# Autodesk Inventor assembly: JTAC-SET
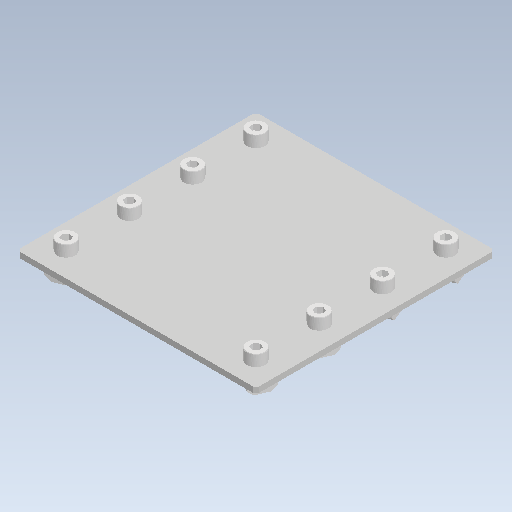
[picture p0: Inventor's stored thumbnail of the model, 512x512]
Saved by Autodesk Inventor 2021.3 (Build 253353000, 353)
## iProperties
Created: 2022-02
Part Number: JTAC-SET
Document SubType Name: Assembly
Designer: kengo
Author: kengo
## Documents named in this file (3)
- C:\Users\kengo\Documents\S2S_frame\SDC345\frame_misumi_ver12\JTAC-SET.iam
- C:\Users\kengo\Documents\S2S_frame\SDC345\frame_misumi_ver12\JTACS-SUD-A170-B170-T4-X17_5-F45-Y17_5-G135-N8-L107_5-V45-S17_5-W135-NA8.ipt
- C:\Users\kengo\Documents\S2S_frame\SDC345\frame_misumi_ver12\CBMHNTT-SET_tuika.iam
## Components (9 placed, 2 different names)
1. JTACS-SUD-A170-B170-T4-X17_5-F45-Y17_5-G135-N8-L107_5-V45-S17_5-W135-NA8:1 — リジッド:1, リジッド:2, リジッド:3, リジッド:4, リジッド:5, リジッド:6, リジッド:7, リジッド:8
2. CBMHNTT-SET_tuika:1 [sub-assembly] — リジッド:1
3. CBMHNTT-SET_tuika:2 [sub-assembly] — リジッド:3
4. CBMHNTT-SET_tuika:3 [sub-assembly] — リジッド:2
5. CBMHNTT-SET_tuika:4 [sub-assembly] — リジッド:7
6. CBMHNTT-SET_tuika:5 [sub-assembly] — リジッド:5
7. CBMHNTT-SET_tuika:6 [sub-assembly] — リジッド:4
8. CBMHNTT-SET_tuika:7 [sub-assembly] — リジッド:8
9. CBMHNTT-SET_tuika:8 [sub-assembly] — リジッド:6
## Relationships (8: WeldJoint 8)
- リジッド:1 [WeldJoint]: JTACS-SUD-A170-B170-T4-X17_5-F45-Y17_5-G135-N8-L107_5-V45-S17_5-W135-NA8:1 ↔ CBMHNTT-SET_tuika:1
- リジッド:2 [WeldJoint]: JTACS-SUD-A170-B170-T4-X17_5-F45-Y17_5-G135-N8-L107_5-V45-S17_5-W135-NA8:1 ↔ CBMHNTT-SET_tuika:3
- リジッド:3 [WeldJoint]: JTACS-SUD-A170-B170-T4-X17_5-F45-Y17_5-G135-N8-L107_5-V45-S17_5-W135-NA8:1 ↔ CBMHNTT-SET_tuika:2
- リジッド:4 [WeldJoint]: JTACS-SUD-A170-B170-T4-X17_5-F45-Y17_5-G135-N8-L107_5-V45-S17_5-W135-NA8:1 ↔ CBMHNTT-SET_tuika:6
- リジッド:5 [WeldJoint]: JTACS-SUD-A170-B170-T4-X17_5-F45-Y17_5-G135-N8-L107_5-V45-S17_5-W135-NA8:1 ↔ CBMHNTT-SET_tuika:5
- リジッド:6 [WeldJoint]: JTACS-SUD-A170-B170-T4-X17_5-F45-Y17_5-G135-N8-L107_5-V45-S17_5-W135-NA8:1 ↔ CBMHNTT-SET_tuika:8
- リジッド:7 [WeldJoint]: JTACS-SUD-A170-B170-T4-X17_5-F45-Y17_5-G135-N8-L107_5-V45-S17_5-W135-NA8:1 ↔ CBMHNTT-SET_tuika:4
- リジッド:8 [WeldJoint]: JTACS-SUD-A170-B170-T4-X17_5-F45-Y17_5-G135-N8-L107_5-V45-S17_5-W135-NA8:1 ↔ CBMHNTT-SET_tuika:7
